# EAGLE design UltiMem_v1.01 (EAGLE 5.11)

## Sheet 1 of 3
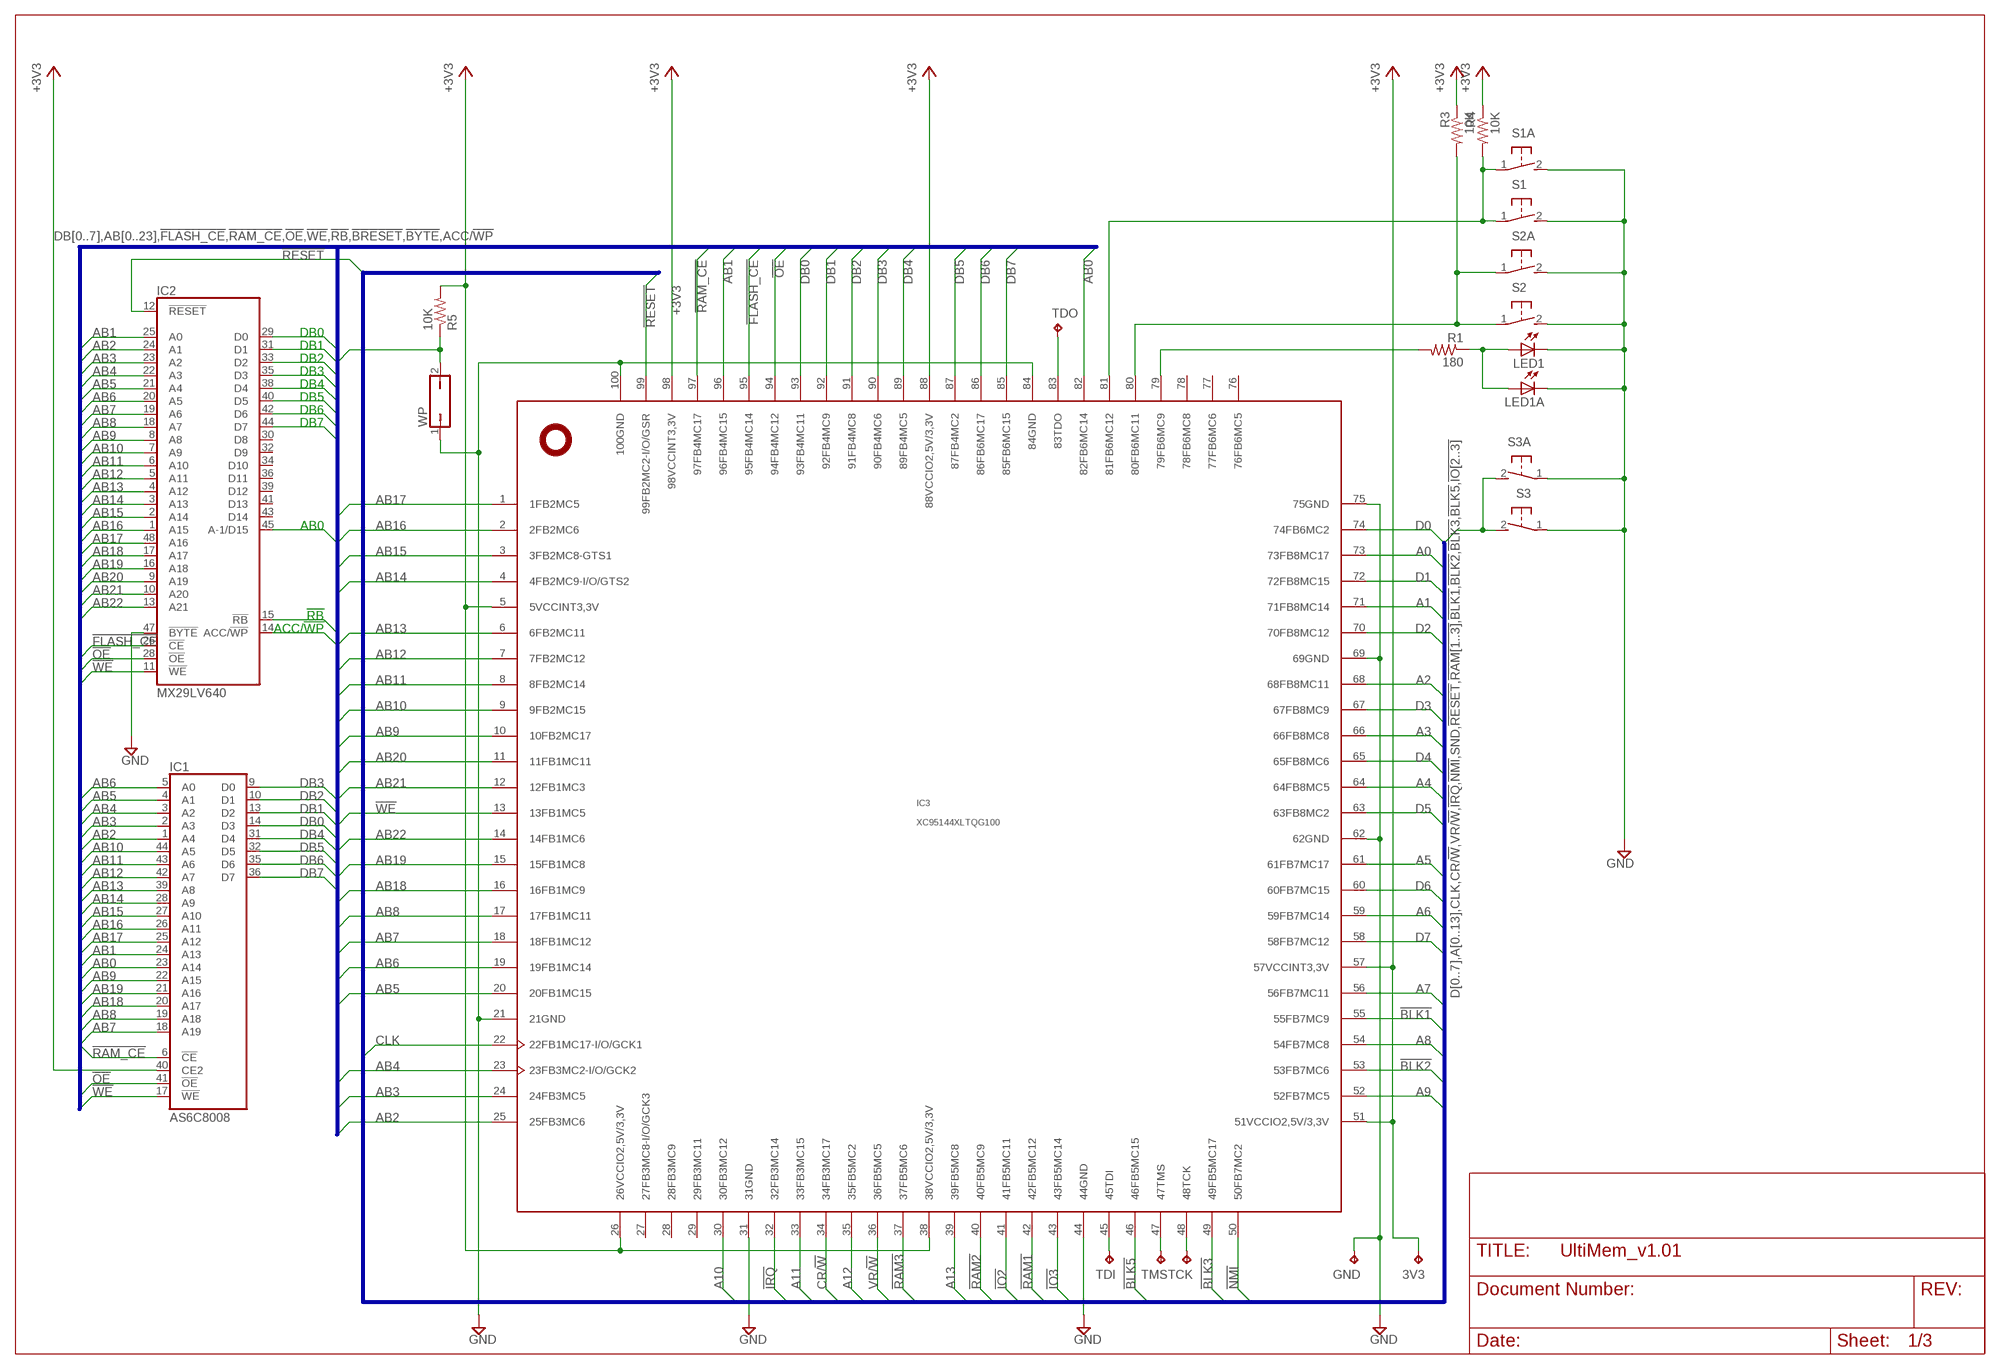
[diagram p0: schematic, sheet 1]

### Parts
3V3  TPTP08R  [TP08R]
GND  TPTP08R  [TP08R]
IC1  AS6C8008  [TSOP44]
IC2  MX29LV640  [TSOP48]
IC3  XC95144XLTQG100  [TQFP100]
LED1  LED3MM  [LED3MM]
LED1A  LED3MM  [LED3MM]
R1  180  R-US_R0402  [R0402]
R3  10K  R-US_R0402  [R0402]
R4  10K  R-US_R0402  [R0402]
R5  10K  R-US_R0402  [R0402]
S1  31-XX  [B3F-31XX]
S1A  31-XX  [B3F-31XX]
S2  31-XX  [B3F-31XX]
S2A  31-XX  [B3F-31XX]
S3  31-XX  [B3F-31XX]
S3A  31-XX  [B3F-31XX]
TCK  TPTP08R  [TP08R]
TDI  TPTP08R  [TP08R]
TDO  TPTP08R  [TP08R]
TMS  TPTP08R  [TP08R]
WP  JP1Q  [JP1]

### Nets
!BLK1: IC3.55(55FB7MC9) ; also sheet 2
!BLK2: IC3.53(53FB7MC6) ; also sheet 2
!BLK3: IC3.49(49FB5MC17) ; also sheet 2
!BLK5: IC3.46(46FB5MC15) ; also sheet 2
!FLASH_CE: IC2.26(!CE) IC3.95(95FB4MC14)
!IO2: IC3.41(41FB5MC11) ; also sheet 2
!IO3: IC3.43(43FB5MC14) ; also sheet 2
!IRQ: IC3.32(32FB3MC14) ; also sheet 2
!NMI: IC3.50(50FB7MC2) ; also sheet 2
!OE: IC1.41(!OE) IC2.28(!OE) IC3.94(94FB4MC12)
!RAM1: IC3.42(42FB5MC12) ; also sheet 2
!RAM2: IC3.40(40FB5MC9) ; also sheet 2
!RAM3: IC3.37(37FB5MC6) ; also sheet 2
!RAM_CE: IC1.6(!CE) IC3.97(97FB4MC17)
!RB: IC2.15(!RB)
!RESET: IC2.12(!RESET) IC3.99(99FB2MC2-I/O/GSR) S3.2(S) S3A.2(S) ; also sheet 2
!WE: IC1.17(!WE) IC2.11(!WE) IC3.13(13FB1MC5)
+3V3: 3V3.TP IC1.40(CE2) IC3.5(5VCCINT3,3V) IC3.26(26VCCIO2,5V/3,3V) IC3.38(38VCCIO2,5V/3,3V) IC3.51(51VCCIO2,5V/3,3V) IC3.57(57VCCINT3,3V) IC3.88(88VCCIO2,5V/3,3V) IC3.98(98VCCINT3,3V) R3.1 R4.1 R5.2 ; also sheet 3
A0: IC3.73(73FB8MC17) ; also sheet 2
A1: IC3.71(71FB8MC14) ; also sheet 2
A2: IC3.68(68FB8MC11) ; also sheet 2
A3: IC3.66(66FB8MC8) ; also sheet 2
A4: IC3.64(64FB8MC5) ; also sheet 2
A5: IC3.61(61FB7MC17) ; also sheet 2
A6: IC3.59(59FB7MC14) ; also sheet 2
A7: IC3.56(56FB7MC11) ; also sheet 2
A8: IC3.54(54FB7MC8) ; also sheet 2
A9: IC3.52(52FB7MC5) ; also sheet 2
A10: IC3.30(30FB3MC12) ; also sheet 2
A11: IC3.33(33FB3MC15) ; also sheet 2
A12: IC3.35(35FB5MC2) ; also sheet 2
A13: IC3.39(39FB5MC8) ; also sheet 2
AB0: IC1.23(A14) IC2.45(A-1/D15) IC3.82(82FB6MC14)
AB1: IC1.24(A13) IC2.25(A0) IC3.96(96FB4MC15)
AB2: IC1.1(A4) IC2.24(A1) IC3.25(25FB3MC6)
AB3: IC1.2(A3) IC2.23(A2) IC3.24(24FB3MC5)
AB4: IC1.3(A2) IC2.22(A3) IC3.23(23FB3MC2-I/O/GCK2)
AB5: IC1.4(A1) IC2.21(A4) IC3.20(20FB1MC15)
AB6: IC1.5(A0) IC2.20(A5) IC3.19(19FB1MC14)
AB7: IC1.18(A19) IC2.19(A6) IC3.18(18FB1MC12)
AB8: IC1.19(A18) IC2.18(A7) IC3.17(17FB1MC11)
AB9: IC1.22(A15) IC2.8(A8) IC3.10(10FB2MC17)
AB10: IC1.44(A5) IC2.7(A9) IC3.9(9FB2MC15)
AB11: IC1.43(A6) IC2.6(A10) IC3.8(8FB2MC14)
AB12: IC1.42(A7) IC2.5(A11) IC3.7(7FB2MC12)
AB13: IC1.39(A8) IC2.4(A12) IC3.6(6FB2MC11)
AB14: IC1.28(A9) IC2.3(A13) IC3.4(4FB2MC9-I/O/GTS2)
AB15: IC1.27(A10) IC2.2(A14) IC3.3(3FB2MC8-GTS1)
AB16: IC1.26(A11) IC2.1(A15) IC3.2(2FB2MC6)
AB17: IC1.25(A12) IC2.48(A16) IC3.1(1FB2MC5)
AB18: IC1.20(A17) IC2.17(A17) IC3.16(16FB1MC9)
AB19: IC1.21(A16) IC2.16(A18) IC3.15(15FB1MC8)
AB20: IC2.9(A19) IC3.11(11FB1MC11)
AB21: IC2.10(A20) IC3.12(12FB1MC3)
AB22: IC2.13(A21) IC3.14(14FB1MC6)
ACC/!WP: IC2.14(ACC/!WP) R5.1 WP.2
CLK: IC3.22(22FB1MC17-I/O/GCK1) ; also sheet 2
CR/!W: IC3.34(34FB3MC17) ; also sheet 2
D0: IC3.74(74FB6MC2) ; also sheet 2
D1: IC3.72(72FB8MC15) ; also sheet 2
D2: IC3.70(70FB8MC12) ; also sheet 2
D3: IC3.67(67FB8MC9) ; also sheet 2
D4: IC3.65(65FB8MC6) ; also sheet 2
D5: IC3.63(63FB8MC2) ; also sheet 2
D6: IC3.60(60FB7MC15) ; also sheet 2
D7: IC3.58(58FB7MC12) ; also sheet 2
DB0: IC1.14(D3) IC2.29(D0) IC3.93(93FB4MC11)
DB1: IC1.13(D2) IC2.31(D1) IC3.92(92FB4MC9)
DB2: IC1.10(D1) IC2.33(D2) IC3.91(91FB4MC8)
DB3: IC1.9(D0) IC2.35(D3) IC3.90(90FB4MC6)
DB4: IC1.31(D4) IC2.38(D4) IC3.89(89FB4MC5)
DB5: IC1.32(D5) IC2.40(D5) IC3.87(87FB4MC2)
DB6: IC1.35(D6) IC2.42(D6) IC3.86(86FB6MC17)
DB7: IC1.36(D7) IC2.44(D7) IC3.85(85FB6MC15)
GND: GND.TP IC2.47(!BYTE) IC3.21(21GND) IC3.31(31GND) IC3.44(44GND) IC3.62(62GND) IC3.69(69GND) IC3.75(75GND) IC3.84(84GND) IC3.100(100GND) LED1.K(C) LED1A.K(C) S1.2(S) S1A.2(S) S2.2(S) S2A.2(S) S3.1(P) S3A.1(P) WP.1 ; also sheet 2,3
N$1: IC3.81(81FB6MC12) R4.2 S1.1(P) S1A.1(P)
N$2: IC3.80(80FB6MC11) R3.2 S2.1(P) S2A.1(P)
N$3: LED1.A LED1A.A R1.1
N$4: IC3.79(79FB6MC9) R1.2
N$5: IC3.45(45TDI) TDI.TP
N$6: IC3.47(47TMS) TMS.TP
N$7: IC3.48(48TCK) TCK.TP
N$8: IC3.83(83TDO) TDO.TP
VR/!W: IC3.36(36FB5MC5) ; also sheet 2
Unconnected: IC2.30(D8) IC2.32(D9) IC2.34(D10) IC2.36(D11) IC2.39(D12) IC2.41(D13) IC2.43(D14) IC3.27(27FB3MC8-I/O/GCK3) IC3.28(28FB3MC9) IC3.29(29FB3MC11) IC3.76(76FB6MC5) IC3.77(77FB6MC6) IC3.78(78FB6MC8)

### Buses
D[0..7],A[0..13],CLK,CR/!W,VR/!W,!IRQ,!NMI,SND,!RESET,!RAM[1..3],!BLK1,!BLK2,!BLK3,!BLK5,!IO[2..3]
DB[0..7],AB[0..23],!FLASH_CE,!RAM_CE,!OE,!WE,!RB,!BRESET,!BYTE,ACC/!WP

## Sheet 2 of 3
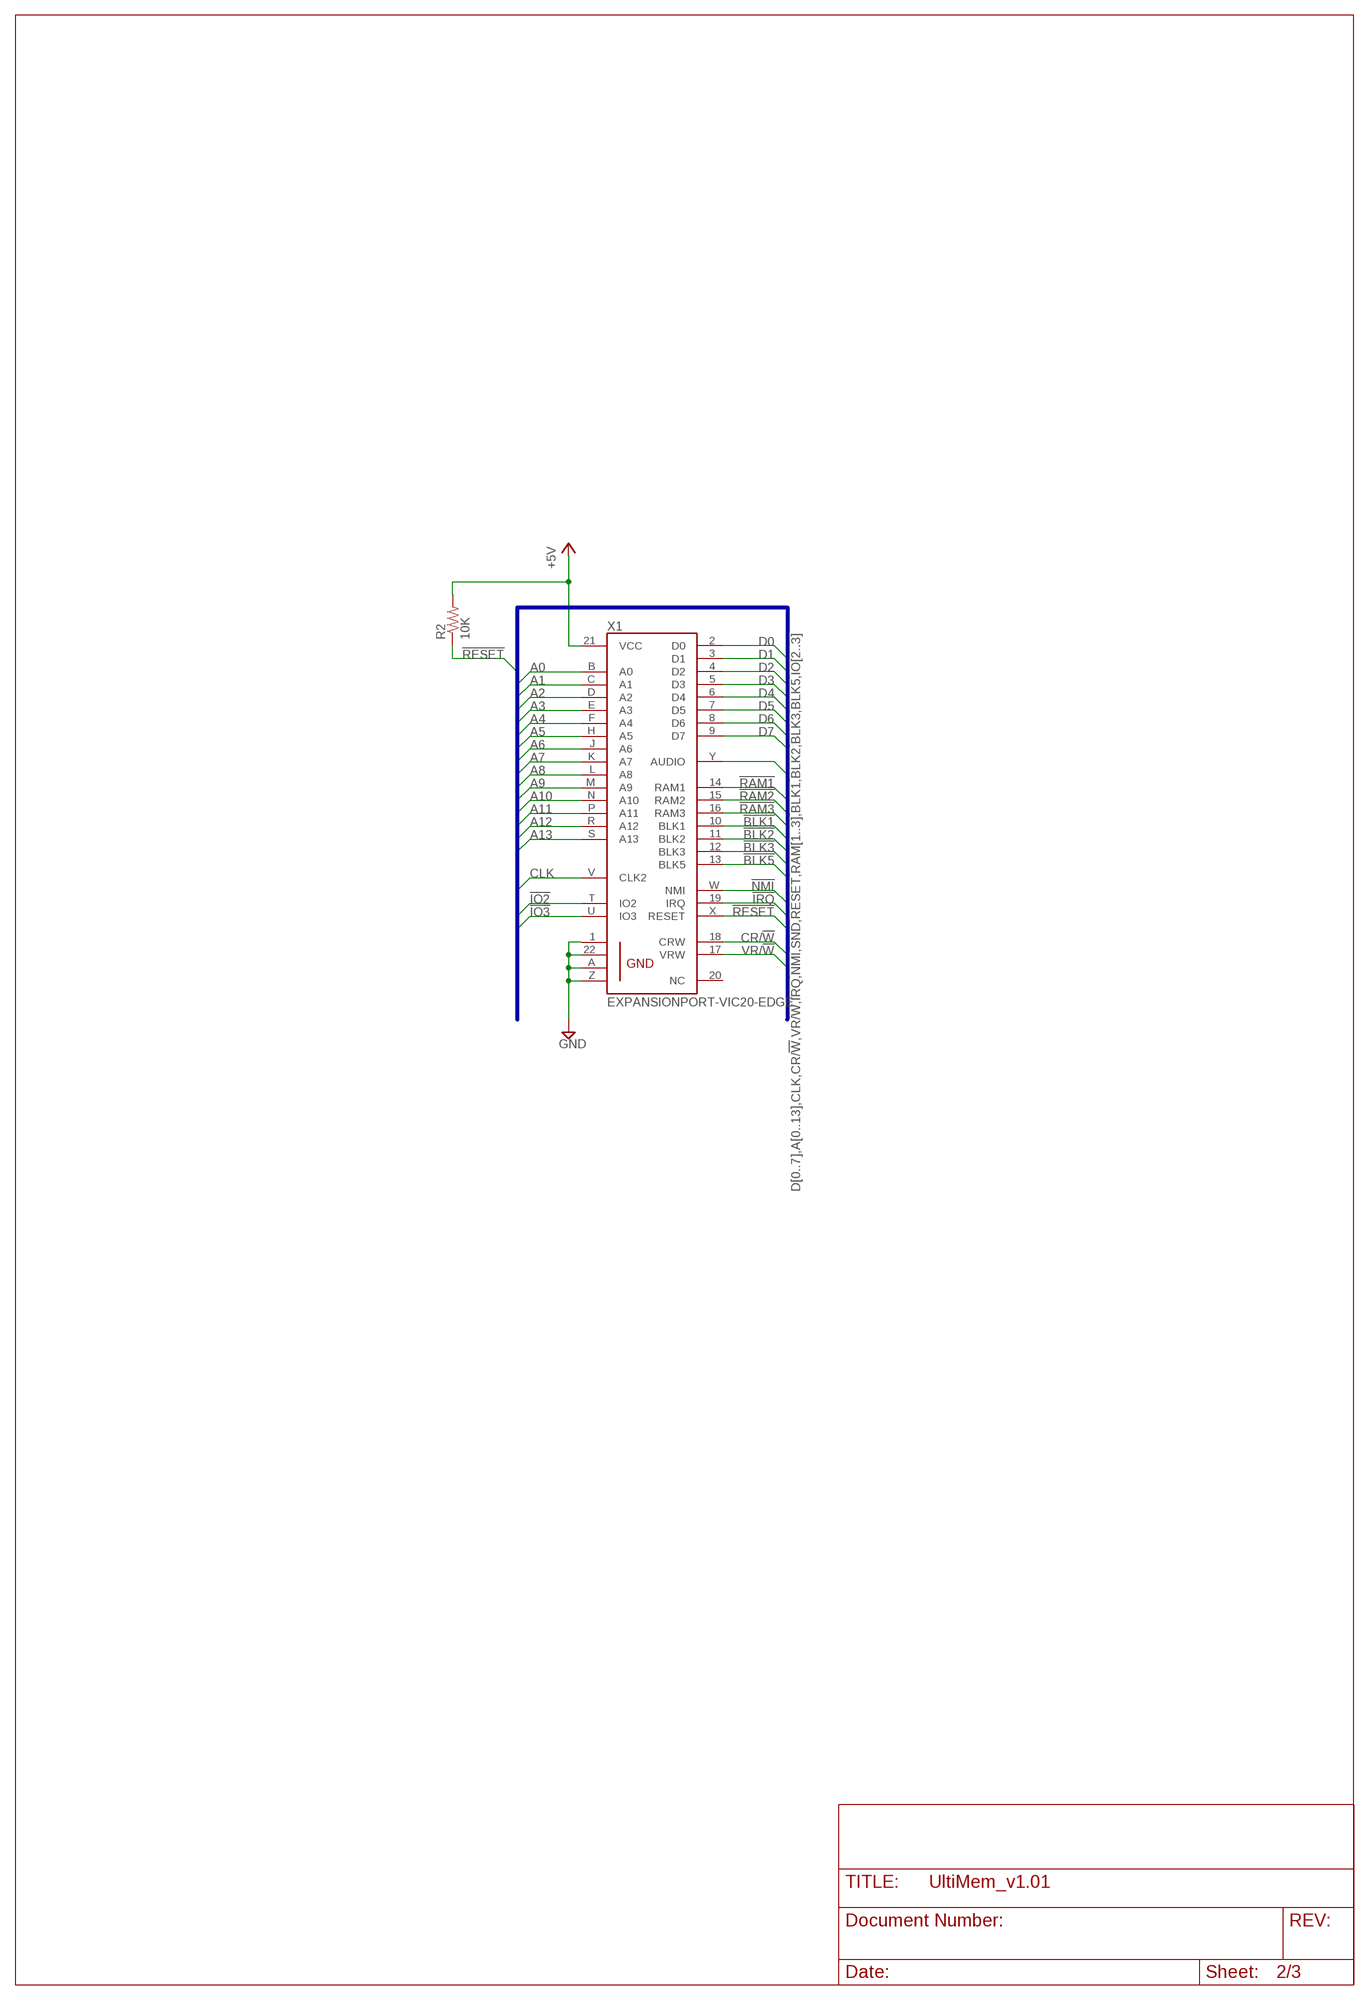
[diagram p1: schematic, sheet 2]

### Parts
R2  10K  R-US_R0402  [R0402]
X1  EXPANSIONPORT-VIC20-EDGE  [MA156-22-2]

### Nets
!BLK1: X1.10(BLK1) ; also sheet 1
!BLK2: X1.11(BLK2) ; also sheet 1
!BLK3: X1.12(BLK3) ; also sheet 1
!BLK5: X1.13(BLK5) ; also sheet 1
!IO2: X1.T(IO2) ; also sheet 1
!IO3: X1.U(IO3) ; also sheet 1
!IRQ: X1.19(IRQ) ; also sheet 1
!NMI: X1.W(NMI) ; also sheet 1
!RAM1: X1.14(RAM1) ; also sheet 1
!RAM2: X1.15(RAM2) ; also sheet 1
!RAM3: X1.16(RAM3) ; also sheet 1
!RESET: R2.1 X1.X(RESET) ; also sheet 1
+5V: R2.2 X1.21(VCC) ; also sheet 3
A0: X1.B(A0) ; also sheet 1
A1: X1.C(A1) ; also sheet 1
A2: X1.D(A2) ; also sheet 1
A3: X1.E(A3) ; also sheet 1
A4: X1.F(A4) ; also sheet 1
A5: X1.H(A5) ; also sheet 1
A6: X1.J(A6) ; also sheet 1
A7: X1.K(A7) ; also sheet 1
A8: X1.L(A8) ; also sheet 1
A9: X1.M(A9) ; also sheet 1
A10: X1.N(A10) ; also sheet 1
A11: X1.P(A11) ; also sheet 1
A12: X1.R(A12) ; also sheet 1
A13: X1.S(A13) ; also sheet 1
CLK: X1.V(CLK2) ; also sheet 1
CR/!W: X1.18(CRW) ; also sheet 1
D0: X1.2(D0) ; also sheet 1
D1: X1.3(D1) ; also sheet 1
D2: X1.4(D2) ; also sheet 1
D3: X1.5(D3) ; also sheet 1
D4: X1.6(D4) ; also sheet 1
D5: X1.7(D5) ; also sheet 1
D6: X1.8(D6) ; also sheet 1
D7: X1.9(D7) ; also sheet 1
GND: X1.1(GND1) X1.22(GND2) X1.A(GND3) X1.Z(GND4) ; also sheet 1,3
SND: X1.Y(AUDIO)
VR/!W: X1.17(VRW) ; also sheet 1
Unconnected: X1.20(NC)

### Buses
D[0..7],A[0..13],CLK,CR/!W,VR/!W,!IRQ,!NMI,SND,!RESET,!RAM[1..3],!BLK1,!BLK2,!BLK3,!BLK5,!IO[2..3]

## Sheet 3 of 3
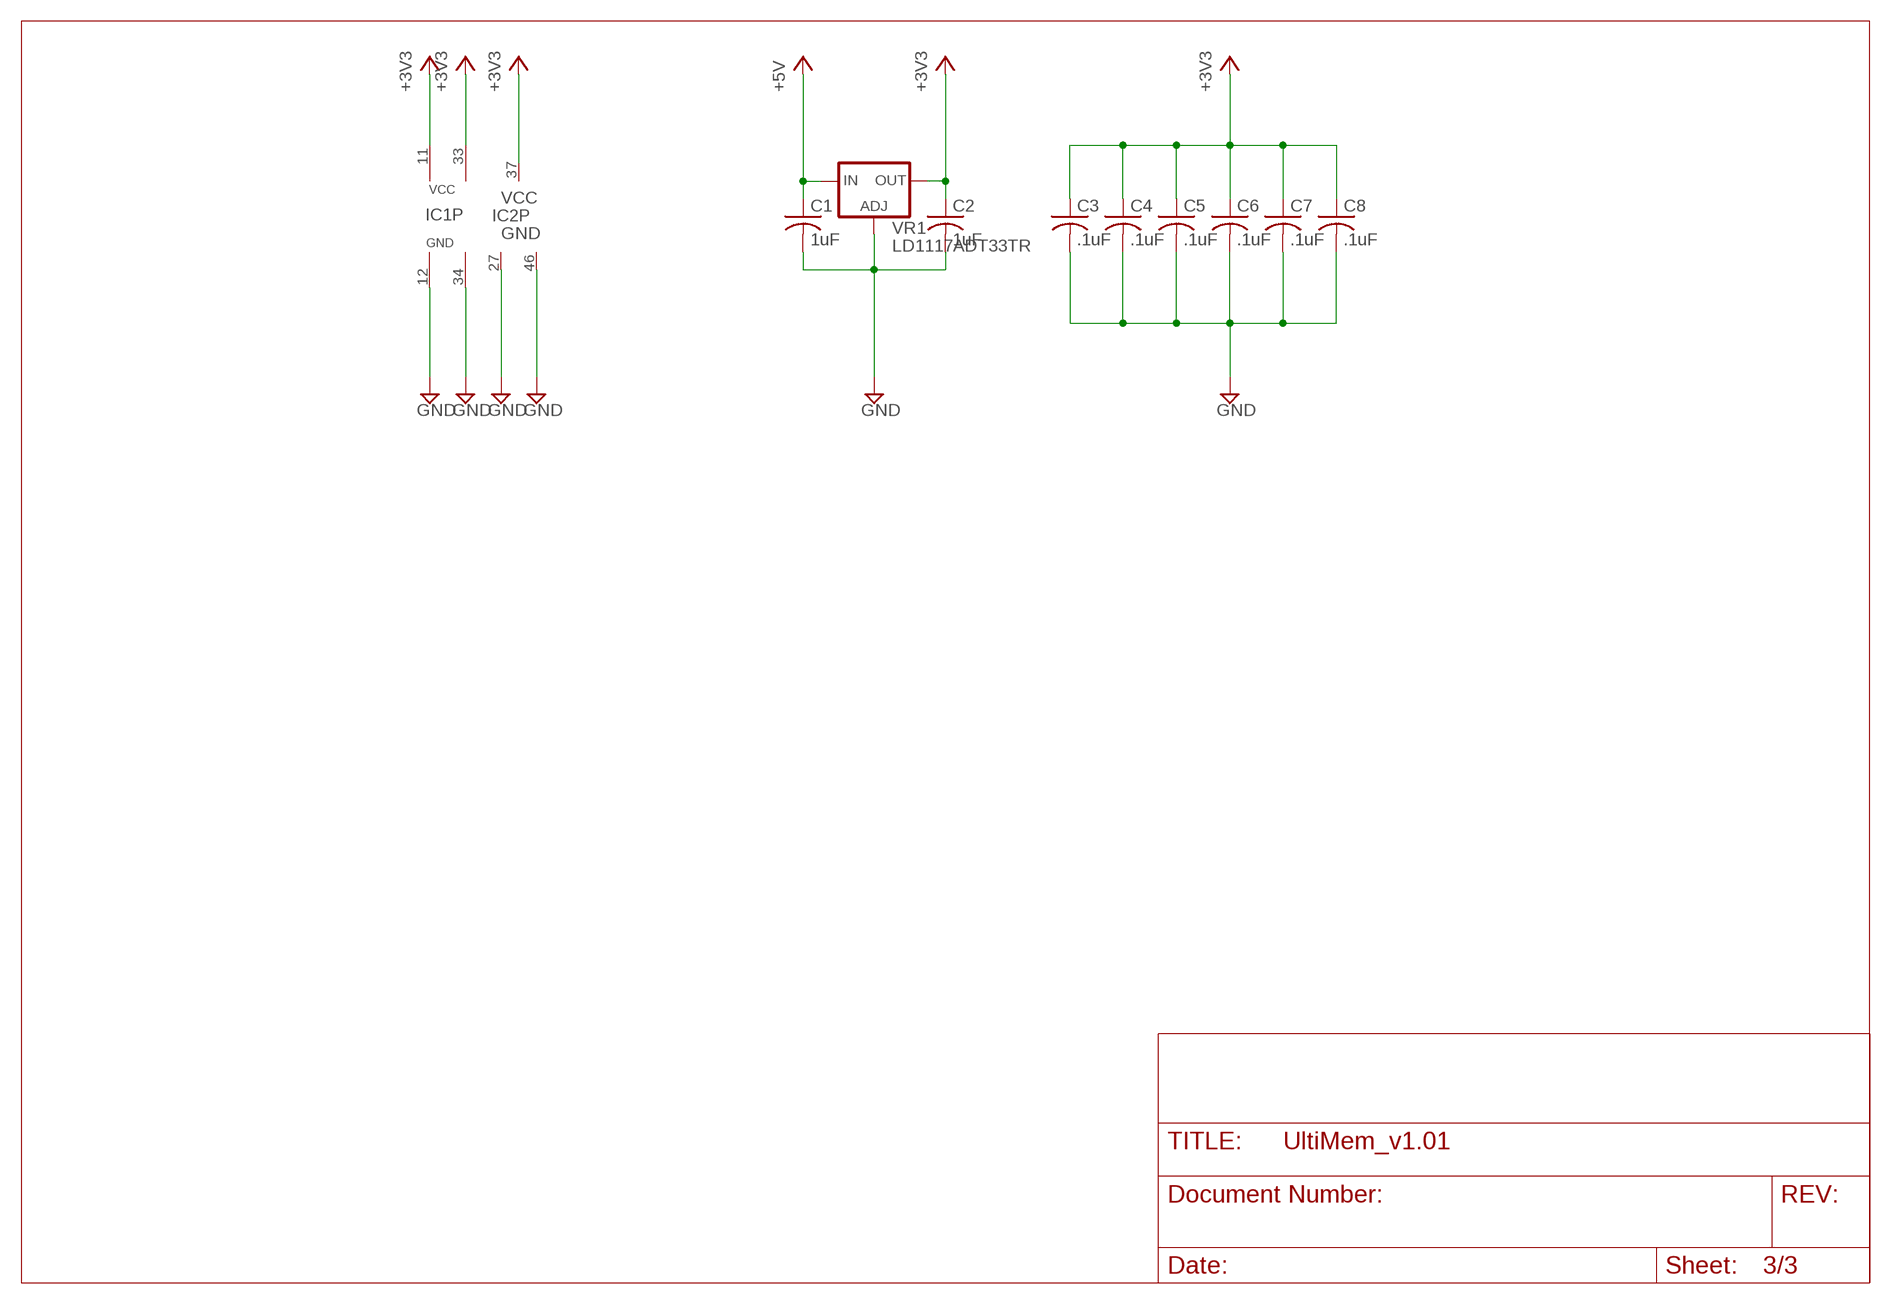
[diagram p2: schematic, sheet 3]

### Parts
C1  1uF  C-USC0402  [C0402]
C2  1uF  C-USC0402  [C0402]
C3  .1uF  C-USC0402  [C0402]
C4  .1uF  C-USC0402  [C0402]
C5  .1uF  C-USC0402  [C0402]
C6  .1uF  C-USC0402  [C0402]
C7  .1uF  C-USC0402  [C0402]
C8  .1uF  C-USC0402  [C0402]
VR1  LD1117ADT33TR  LD117ADT33TR  [DPACK]

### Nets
+3V3: C2.1 C3.1 C4.1 C5.1 C6.1 C7.1 C8.1 IC1.11(VCC) IC1.33(VCC) IC2.37(VCC) VR1.4(OUT) ; also sheet 1
+5V: C1.1 VR1.3(IN) ; also sheet 2
GND: C1.2 C2.2 C3.2 C4.2 C5.2 C6.2 C7.2 C8.2 IC1.12(GND) IC1.34(GND) IC2.27(GND) IC2.46(GND) VR1.1(ADJ) ; also sheet 1,2

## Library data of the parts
3V3 GND TCK TDI TDO TMS = testpad:TP: Test pad
C1-C8 = rcl:C-US: CAPACITOR, American symbol
IC1 = memory--alliance:AS6C8008
IC2 = memory-macronix:MX29LV640
IC3 = xilinx_xc95XXXxl:XC95144XLTQG100
LED1 LED1A = led:LED: LED
R1 R3-R5 = rcl:R-US_: RESISTOR, American symbol
R2 = resistor:R-US_: RESISTOR, American symbol
S1 S1A S2 S2A S3 S3A = switch-omron:31-XX: OMRON SWITCH; MPN: B3F-3100; OC_FARNELL: 959704; OC_NEWARK: 36M3582
VR1 = v-reg:LD117A?*: Low drop fixed and adjustable positive voltage regulators 1 A Source: http://www.st.com/stonline/products/literature/ds/7194/ld1117axx.pdf
WP = jumper:JP1Q: JUMPER
X1 = 0RB_Commodore:EXPANSIONPORT-VIC20-EDGE: Expansionport for the Commodore VIC-20, edge version

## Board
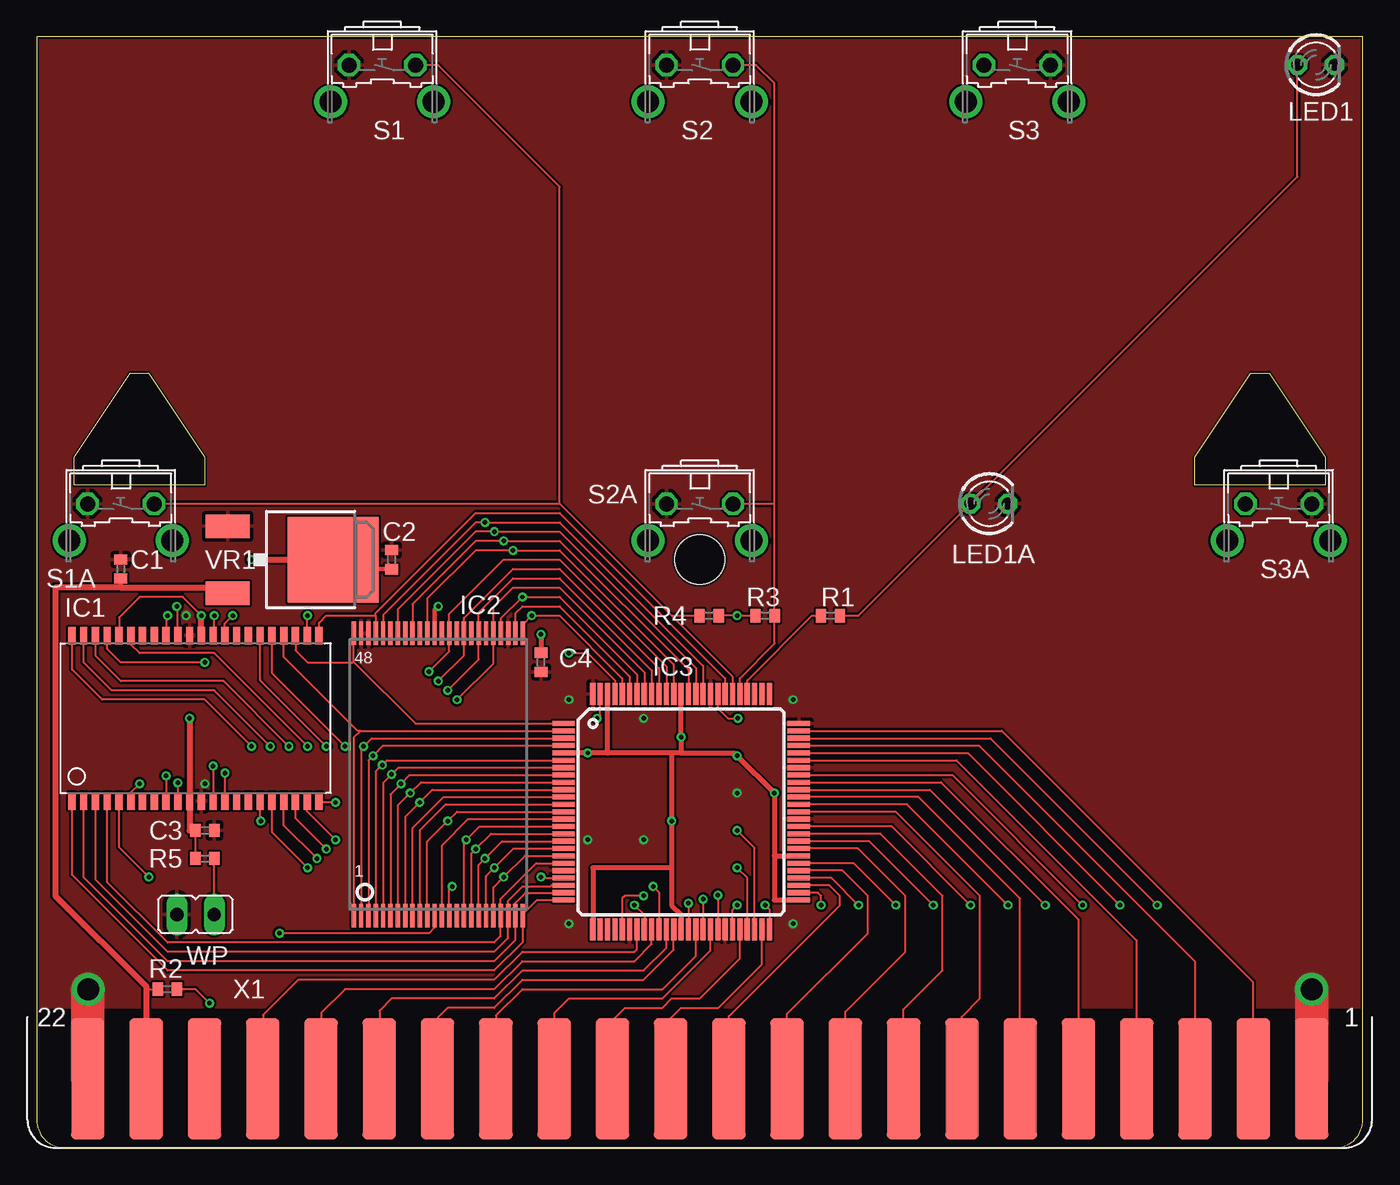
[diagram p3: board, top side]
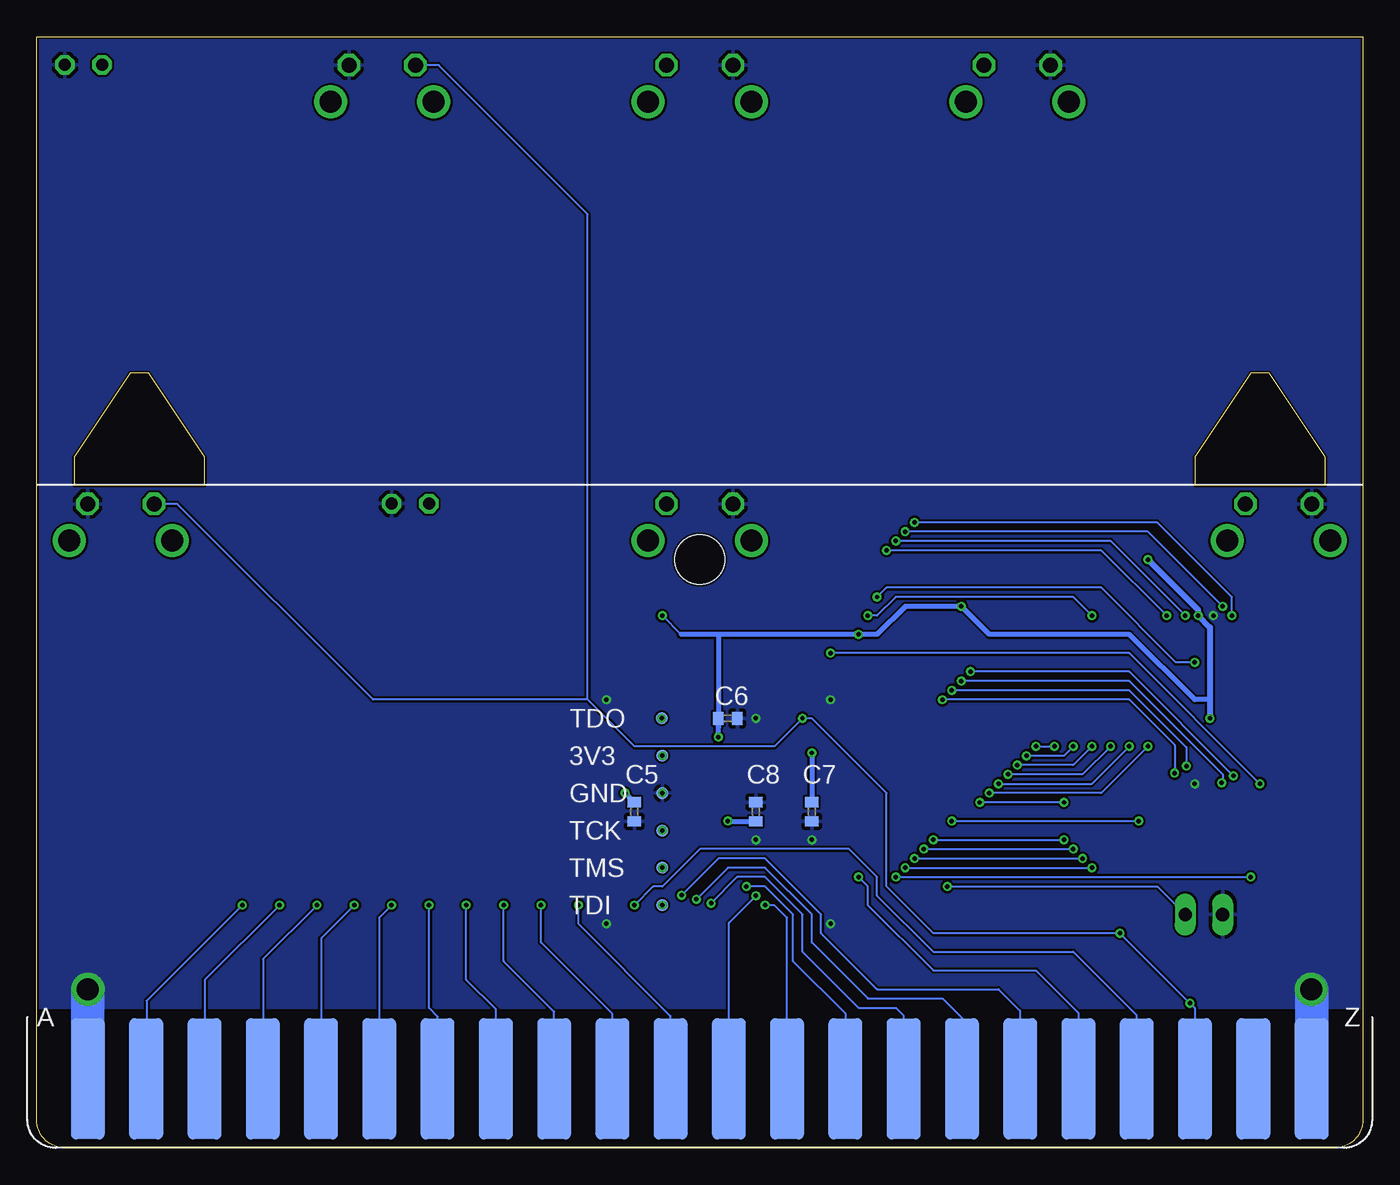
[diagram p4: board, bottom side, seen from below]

Size 90.17 x 75.56 mm. Coordinates in mm from the lower left corner, seen from the top.
Outline: 90.17,75.56 0,75.56 0,1.91 arc90 1.91,0 88.27,0 arc90 90.17,1.91 90.17,75.56
Outline: 2.54,45.09 2.54,46.99 6.35,52.7 7.62,52.7 11.43,46.99 11.43,45.09 2.54,45.09
Outline: 78.74,45.09 78.74,46.99 82.55,52.7 83.82,52.7 87.63,46.99 87.63,45.09 78.74,45.09
Copper layers (1*16): Top 0.035mm / dielectric 1.5mm / Bottom 0.035mm
Design rules "hackvana *": minimum track width 6mil, minimum drill 0.3mm, track to track 0.1501mm, track to pad 0.1501mm, pad to pad 0.1501mm, via to via 0.1501mm, smd to smd 0mil, copper to edge 6mil, drill to drill 6mil, minimum pad ring 10mil, minimum via ring 6mil, stop-mask expansion 2mil, vias tented up to drill 100mil, thermal gap 10mil
Holes 3.38 mm at 45.09,40.01

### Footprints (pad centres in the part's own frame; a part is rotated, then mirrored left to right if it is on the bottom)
TP08R = smd 0.8 x 0.8: TP 0,0
C0402 = smd 0.7 x 0.9: 1 -0.65,0; 2 0.65,0
TSOP44 = smd 0.5 x 1.2: 1 -8.4,-5.627; 2 -7.6,-5.627; 3 -6.8,-5.627; 4 -6,-5.627; 5 -5.2,-5.627; 6 -4.4,-5.627; 7 -3.6,-5.627; 8 -2.8,-5.627; 9 -2,-5.627; 10 -1.2,-5.627; 11 -0.4,-5.627; 12 0.4,-5.627; 13 1.2,-5.627; 14 2,-5.627; 15 2.8,-5.627; 16 3.6,-5.627; 17 4.4,-5.627; 18 5.2,-5.627; 19 6,-5.627; 20 6.8,-5.627; 21 7.6,-5.627; 22 8.4,-5.627; 23 8.4,5.627; 24 7.6,5.627; 25 6.8,5.627; 26 6,5.627; 27 5.2,5.627; 28 4.4,5.627; 29 3.6,5.627; 30 2.8,5.627; 31 2,5.627; 32 1.2,5.627; 33 0.4,5.627; 34 -0.4,5.627; 35 -1.2,5.627; 36 -2,5.627; 37 -2.8,5.627; 38 -3.6,5.627; 39 -4.4,5.627; 40 -5.2,5.627; 41 -6,5.627; 42 -6.8,5.627; 43 -7.6,5.627; 44 -8.4,5.627
TSOP48 = smd 1.6 x 0.3: 1 -9.6,5.75; 2 -9.6,5.25; 3 -9.6,4.75; 4 -9.6,4.25; 5 -9.6,3.75; 6 -9.6,3.25; 7 -9.6,2.75; 8 -9.6,2.25; 9 -9.6,1.75; 10 -9.6,1.25; 11 -9.6,0.75; 12 -9.6,0.25; 13 -9.6,-0.25; 14 -9.6,-0.75; 15 -9.6,-1.25; 16 -9.6,-1.75; 17 -9.6,-2.25; 18 -9.6,-2.75; 19 -9.6,-3.25; 20 -9.6,-3.75; 21 -9.6,-4.25; 22 -9.6,-4.75; 23 -9.6,-5.25; 24 -9.6,-5.75; 25 9.6,-5.75; 26 9.6,-5.25; 27 9.6,-4.75; 28 9.6,-4.25; 29 9.6,-3.75; 30 9.6,-3.25; 31 9.6,-2.75; 32 9.6,-2.25; 33 9.6,-1.75; 34 9.6,-1.25; 35 9.6,-0.75; 36 9.6,-0.25; 37 9.6,0.25; 38 9.6,0.75; 39 9.6,1.25; 40 9.6,1.75; 41 9.6,2.25; 42 9.6,2.75; 43 9.6,3.25; 44 9.6,3.75; 45 9.6,4.25; 46 9.6,4.75; 47 9.6,5.25; 48 9.6,5.75
TQFP100 = smd 1.5 x 0.35: 1 -8,6; 2 -8,5.5; 3 -8,5; 4 -8,4.5; 5 -8,4; 6 -8,3.5; 7 -8,3; 8 -8,2.5; 9 -8,2; 10 -8,1.5; 11 -8,1; 12 -8,0.5; 13 -8,0; 14 -8,-0.5; 15 -8,-1; 16 -8,-1.5; 17 -8,-2; 18 -8,-2.5; 19 -8,-3; 20 -8,-3.5; 21 -8,-4; 22 -8,-4.5; 23 -8,-5; 24 -8,-5.5; 25 -8,-6; 51 8,-6; 52 8,-5.5; 53 8,-5; 54 8,-4.5; 55 8,-4; 56 8,-3.5; 57 8,-3; 58 8,-2.5; 59 8,-2; 60 8,-1.5; 61 8,-1; 62 8,-0.5; 63 8,0; 64 8,0.5; 65 8,1; 66 8,1.5; 67 8,2; 68 8,2.5; 69 8,3; 70 8,3.5; 71 8,4; 72 8,4.5; 73 8,5; 74 8,5.5; 75 8,6 | smd 0.35 x 1.5: 26 -6,-8; 27 -5.5,-8; 28 -5,-8; 29 -4.5,-8; 30 -4,-8; 31 -3.5,-8; 32 -3,-8; 33 -2.5,-8; 34 -2,-8; 35 -1.5,-8; 36 -1,-8; 37 -0.5,-8; 38 0,-8; 39 0.5,-8; 40 1,-8; 41 1.5,-8; 42 2,-8; 43 2.5,-8; 44 3,-8; 45 3.5,-8; 46 4,-8; 47 4.5,-8; 48 5,-8; 49 5.5,-8; 50 6,-8; 76 6,8; 77 5.5,8; 78 5,8; 79 4.5,8; 80 4,8; 81 3.5,8; 82 3,8; 83 2.5,8; 84 2,8; 85 1.5,8; 86 1,8; 87 0.5,8; 88 0,8; 89 -0.5,8; 90 -1,8; 91 -1.5,8; 92 -2,8; 93 -2.5,8; 94 -3,8; 95 -3.5,8; 96 -4,8; 97 -4.5,8; 98 -5,8; 99 -5.5,8; 100 -6,8
LED3MM = drill 0.813 octagon: A -1.27,0; K 1.27,0
R0402 = smd 0.7 x 0.9: 1 -0.65,0; 2 0.65,0
B3F-31XX = drill 1.016 octagon: 1 -2.261,-1.245; 2 2.261,-1.245 | drill 1.499 pad 2.159: 3 -3.505,1.245; 4 3.505,1.245
DPACK = smd 1.6 x 3: 1 -2.28,-4.8; 3 2.28,-4.8 | smd 5.8 x 6.2: 4 0,2.38
JP1 = drill 0.914 long: 1 0,-1.27; 2 0,1.27
MA156-22-2 = smd 2.286 x 8.255: 1 41.605,-0.381; 2 37.643,-0.381; 3 33.68,-0.381; 4 29.718,-0.381; 5 25.756,-0.381; 6 21.793,-0.381; 7 17.831,-0.381; 8 13.868,-0.381; 9 9.906,-0.381; 10 5.944,-0.381; 11 1.981,-0.381; 12 -1.981,-0.381; 13 -5.944,-0.381; 14 -9.906,-0.381; 15 -13.868,-0.381; 16 -17.831,-0.381; 17 -21.793,-0.381; 18 -25.756,-0.381; 19 -29.718,-0.381; 20 -33.68,-0.381; 21 -37.643,-0.381; 22 -41.605,-0.381 | smd 2.286 x 8.255 bottom: A 41.605,-0.381; B 37.643,-0.381; C 33.68,-0.381; D 29.718,-0.381; E 25.756,-0.381; F 21.793,-0.381; H 17.831,-0.381; J 13.868,-0.381; K 9.906,-0.381; L 5.944,-0.381; M 1.981,-0.381; N -1.981,-0.381; P -5.944,-0.381; R -9.906,-0.381; S -13.868,-0.381; T -17.831,-0.381; U -21.793,-0.381; V -25.756,-0.381; W -29.718,-0.381; X -33.68,-0.381; Y -37.643,-0.381; Z -41.605,-0.381

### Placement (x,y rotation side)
3V3  47.62,26.67 90 bottom
C1  5.72,39.37 90 top
C2  24.13,40.01 90 top
C3  11.43,21.59 0 top
C4  34.29,33.02 270 top
C5  49.53,22.86 270 bottom
C6  43.18,29.21 0 bottom
C7  37.47,22.86 270 bottom
C8  41.27,22.86 90 bottom
GND  47.62,24.13 90 bottom
IC1  10.8,29.21 0 top
IC2  27.3,25.4 90 top
IC3  43.81,22.86 0 top
LED1  87,73.66 0 top
LED1A  64.77,43.81 0 top
R1  53.98,36.2 180 top
R2  8.89,10.79 180 top
R3  49.53,36.2 0 top
R4  45.72,36.2 180 top
R5  11.43,19.68 180 top
S1  23.5,72.39 180 top
S1A  5.72,42.55 180 top
S2  45.09,72.39 180 top
S2A  45.09,42.55 180 top
S3  66.67,72.39 180 top
S3A  84.45,42.55 180 top
TCK  47.62,21.59 90 bottom
TDI  47.62,16.51 90 bottom
TDO  47.68,29.21 90 bottom
TMS  47.62,19.05 90 bottom
VR1  17.78,40.01 270 top
WP  10.8,15.88 270 top
X1  45.09,5.08 0 top

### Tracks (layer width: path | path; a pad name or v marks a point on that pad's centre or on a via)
!BLK1
  Top 0.152: IC3.55 54.8,18.86 56.52,17.14 56.52,14.61 51.02,9.11 X1.10
!BLK2
  Top 0.152: IC3.53 53.9,17.86 54.61,17.14 54.61,16.51 47.06,8.96 X1.11
!BLK3
  Top 0.152: X1.12 43.1,8.81 43.81,9.53 46.36,9.53 49.31,12.48 IC3.49
!BLK5
  Top 0.152: IC3.46 47.81,12.89 45.09,10.16 43.18,10.16 42.55,9.53 40.01,9.53 39.14,8.66 X1.13
!FLASH_CE
  Top 0.152: IC2.26 32.55,36.37 33.02,36.83 35.56,36.83 40.31,32.08 IC3.95
!IO2  (via drill 0.3)
  Top 0.152: v45.31,16.91 IC3.41
  Bottom 0.152: v45.31,16.91 43.18,19.05 40.64,19.05 37.47,15.88 37.47,13.97 33.66,10.16 28.57,10.16 27.26,8.85 X1.T
!IO3  (via drill 0.3)
  Top 0.152: v46.31,17.18 IC3.43
  Bottom 0.152: v46.31,17.18 43.81,19.68 40.64,19.68 36.83,15.88 36.83,14.61 33.02,10.79 24.77,10.79 23.3,9.33 23.3,4.71 X1.U
!IRQ
  Top 0.152: IC3.32 40.81,13.51 40.64,13.34 33.02,13.34 31.12,11.43 17.78,11.43 15.38,9.03 15.38,4.72 X1.19
!NMI  (via drill 0.3)
  Top 0.152: v49.53,16.51 49.81,16.23 IC3.50
  Bottom 0.152: v49.53,16.51 48.26,17.78 47.62,17.78 45.09,20.32 34.92,20.32 33.02,18.41 33.02,17.14 29.21,13.34 19.69,13.34 15.38,9.03 15.38,4.72 X1.W
!OE  (via drill 0.3)
  Top 0.152: IC2.28 31.55,36 v33.02,37.47 35.56,37.47 40.81,32.21 IC3.94 | IC1.41 4.8,33.94 5.72,33.02 v11.43,33.02
  Bottom 0.152: v11.43,33.02 12.7,33.02 17.78,38.1 32.39,38.1 v33.02,37.47
!RAM1
  Top 0.152: IC3.42 45.81,13.43 42.55,10.16 36.2,10.16 35.18,9.15 X1.14
!RAM2
  Top 0.152: IC3.40 44.81,13.06 42.55,10.79 33.02,10.79 31.22,9 X1.15
!RAM3
  Top 0.152: IC3.37 43.31,13.47 41.27,11.43 33.02,11.43 31.12,9.53 27.94,9.53 27.26,8.85 X1.16
!RAM_CE  (via drill 0.3)
  Top 0.152: IC1.6 6.4,24.18 v6.98,24.77 | IC3.97 39.31,31.8 37.47,33.66 v36.2,33.66
  Bottom 0.152: v6.98,24.77 15.88,33.66 v36.2,33.66
!RESET  (via drill 0.3)
  Top 0.152: v38.1,29.21 38.31,29.43 IC3.99 | R2.1 10.8,10.79 v11.75,9.84 | IC2.12 27.05,14.99 26.67,14.61 v16.51,14.61
  Bottom 0.152: X1.X 11.42,4.72 11.42,9.52 v11.75,9.84 v16.51,14.61 29.21,14.61 32.39,17.78 32.39,24.13 37.47,29.21 v38.1,29.21 40.01,27.3 49.53,27.3 52.7,30.48 | S3.2 62.84,73.64 52.7,63.5 52.7,30.48 | S3A.2 80.62,43.79 67.31,30.48 52.7,30.48
!WE  (via drill 0.3)
  Top 0.152: IC2.11 26.55,20.84 v27.94,22.23 28.57,22.86 IC3.13 | IC1.17 15.2,22.27 v15.24,22.23
  Bottom 0.152: v27.94,22.23 v15.24,22.23
+3V3  (via drill 0.3)
  Top 0.152: IC1.40 5.59,36.08 6.98,37.47 9.93,37.47 v11.2,36.2 | R4.1 v47.62,36.2 R3.1 | C3.1 R5.2
  Top 0.305: IC2.37 27.05,36.58 v27.3,36.83 | C2.1 20.81,39.35 arc-90 VR1.4
  Top 0.33: 38.81,26.86 IC3.98 | IC3.5 v37.47,26.86 38.81,26.86 | IC3.51 50.16,16.86 50.16,19.86 | 50.16,19.86 IC3.57 | 50.16,19.86 v50.16,24.13 3V3.TP 47.44,26.86 43.81,26.86 | IC3.88 v43.81,27.94 43.81,26.86 | 43.18,26.86 38.81,26.86 | 43.81,26.86 43.18,26.86 | IC3.38 43.81,15.88 43.18,16.51 43.18,19.05 | 43.18,26.86 v43.18,22.23 43.18,19.05 | IC3.26 37.81,19.05 43.18,19.05
  Top 0.356: v34.29,34.92 C4.1
  Top 0.406: IC1.33 v11.2,36.2 | v10.4,29.21 IC1.11 10.4,21.59 C3.1 | v14.61,40.01 VR1.4
  Bottom 0.152: 46.36,34.92 v47.62,36.2
  Bottom 0.33: C6.1 43.83,27.95 | 43.81,34.92 43.81,29.21
  Bottom 0.356: v37.47,26.86 C7.1 | C8.1 43.16,22.21 v43.18,22.23 | 43.83,27.95 v43.81,27.94 | C5.1 v50.16,24.13 | 10.4,30.48 11.43,30.48 15.88,34.92 25.4,34.92 v27.3,36.83 31.12,36.83 33.02,34.92 v34.29,34.92 43.81,34.92 46.36,34.92 | 43.81,28.57 43.81,29.21 C6.1
  Bottom 0.406: v10.4,29.21 10.4,30.48 10.4,35.4 v11.2,36.2 11.2,36.59 v14.61,40.01
  other vias: 47.62,26.67
+5V
  Top 0.152: 7.46,10.79 R2.2
  Top 0.305: C1.1 5.72,38.1
  Top 0.406: 7.44,10.97 7.46,10.95 | 12.7,38.1 5.72,38.1 1.27,38.1 1.27,17.14 7.44,10.97 | 7.44,10.79 7.46,10.79 | 7.44,10.79 X1.21 | 7.44,10.97 7.44,10.79
  Top 0.813: 12.7,38.1 12.7,37.73 VR1.3
A0  (via drill 0.3)
  Top 0.152: IC3.73 64.85,27.86 v76.2,16.51
  Bottom 0.152: v76.2,16.51 82.7,10.01 82.7,4.72 X1.B
A1  (via drill 0.3)
  Top 0.152: IC3.71 63.31,26.86 v73.66,16.51
  Bottom 0.152: v73.66,16.51 78.74,11.43 78.74,4.72 X1.C
A2  (via drill 0.3)
  Top 0.152: IC3.68 62.27,25.36 v71.12,16.51
  Bottom 0.152: v71.12,16.51 74.78,12.85 74.78,4.72 X1.D
A3  (via drill 0.3)
  Top 0.152: IC3.66 60.73,24.36 v68.58,16.51
  Bottom 0.152: v68.58,16.51 70.82,14.27 70.82,4.72 X1.E
A4  (via drill 0.3)
  Top 0.152: IC3.64 59.19,23.36 v66.04,16.51
  Bottom 0.152: v66.04,16.51 66.86,15.69 66.86,4.71 X1.F
A5  (via drill 0.3)
  Top 0.152: IC3.61 58.15,21.86 v63.5,16.51
  Bottom 0.152: v63.5,16.51 63.5,9.53 62.9,8.93 62.9,4.71 X1.H
A6  (via drill 0.3)
  Top 0.152: IC3.59 56.61,20.86 v60.96,16.51
  Bottom 0.152: v60.96,16.51 60.96,11.43 58.94,9.41 X1.J
A7  (via drill 0.3)
  Top 0.152: IC3.56 55.57,19.36 v58.42,16.51
  Bottom 0.152: v58.42,16.51 58.42,12.7 54.98,9.26 54.98,4.71 X1.K
A8  (via drill 0.3)
  Top 0.152: IC3.54 54.03,18.36 v55.88,16.51
  Bottom 0.152: v55.88,16.51 55.88,13.97 51.02,9.11 X1.L
A9  (via drill 0.3)
  Top 0.152: IC3.52 53.12,17.36 53.34,17.14 v53.34,16.51
  Bottom 0.152: v53.34,16.51 53.34,15.24 47.06,8.96 X1.M
A10  (via drill 0.3)
  Top 0.152: IC3.30 39.81,16.95 40.01,17.14 v41.27,17.14
  Bottom 0.152: X1.N 43.1,15.32 v41.27,17.14
A11  (via drill 0.3)
  Top 0.152: IC3.33 41.31,15.84 v40.64,16.51
  Bottom 0.152: v40.64,16.51 40.01,16.51 39.14,15.65 X1.P
A12  (via drill 0.3)
  Top 0.152: IC3.35 42.31,17.38 v41.91,17.78
  Bottom 0.152: v41.91,17.78 40.64,17.78 38.73,15.88 38.73,12.7 35.18,9.15 X1.R
A13  (via drill 0.3)
  Top 0.152: v44.31,16.64 IC3.39
  Bottom 0.152: v44.31,16.64 42.55,18.41 40.64,18.41 38.1,15.88 38.1,13.34 34.29,9.53 31.75,9.53 31.22,9 X1.S
AB0
  Top 0.152: 23.05,36.2 IC2.45 | 23.05,36.2 23.05,36.39 29.84,43.18 35.56,43.18 46.81,31.93 IC3.82 | IC1.23 19.2,35.7 19.69,36.2 23.05,36.2
AB1  (via drill 0.3)
  Top 0.152: IC1.24 18.39,36.17 v18.41,36.2 | IC2.25 33.05,35.59 v33.66,36.2 35.56,36.2 39.81,31.94 IC3.96
  Bottom 0.152: v33.66,36.2 33.02,36.2 31.75,37.47 19.69,37.47 v18.41,36.2
AB2
  Top 0.152: IC3.25 34.01,16.86 33.05,15.91 IC2.24 33.05,14.01 31.12,12.06 8.89,12.06 2.4,18.56 IC1.1
AB3
  Top 0.152: IC3.24 33.23,17.36 32.55,16.68 IC2.23 32.55,14.14 31.12,12.7 8.89,12.7 3.2,18.39 IC1.2
AB4
  Top 0.152: IC3.23 35.01,17.86 34.92,17.78 33.02,17.78 32.05,16.82 IC2.22 32.05,14.28 31.12,13.34 8.89,13.34 3.99,18.23 IC1.3
AB5
  Top 0.152: IC3.20 33.97,19.36 31.55,16.95 IC2.21 31.55,14.41 31.12,13.97 8.89,13.97 4.8,18.07 IC1.4
AB6  (via drill 0.3)
  Top 0.152: IC2.20 31.05,17.72 v31.75,18.41 33.2,19.86 IC3.19 | IC1.5 5.59,20.44 v7.62,18.41
  Bottom 0.152: v31.75,18.41 v7.62,18.41
AB7  (via drill 0.3)
  Top 0.152: IC2.19 30.55,18.49 v31.12,19.05 32.42,20.36 IC3.18 | IC1.18 16,21.47 v18.41,19.05
  Bottom 0.152: v31.12,19.05 v18.41,19.05
AB8  (via drill 0.3)
  Top 0.152: IC2.18 30.05,19.26 v30.48,19.68 31.66,20.86 IC3.17 | IC1.19 16.8,21.94 v19.05,19.68
  Bottom 0.152: v30.48,19.68 v19.05,19.68
AB9  (via drill 0.3)
  Top 0.152: IC2.8 25.05,22.52 v26.04,23.5 26.9,24.36 IC3.10 | v20.32,23.5 19.28,23.5 IC1.22
  Bottom 0.152: v20.32,23.5 v26.04,23.5
AB10  (via drill 0.3)
  Top 0.152: IC2.7 24.55,23.29 v25.4,24.13 26.13,24.86 IC3.9 | IC1.44 2.4,32.53 4.45,30.48 11.43,30.48 v14.61,27.3
  Bottom 0.152: v14.61,27.3 17.78,24.13 v25.4,24.13
AB11  (via drill 0.3)
  Top 0.152: IC2.6 24.05,24.05 v24.77,24.77 25.36,25.36 IC3.8 | IC1.43 3.2,33 5.08,31.11 12.06,31.11 v15.88,27.3
  Bottom 0.152: v15.88,27.3 18.41,24.77 v24.77,24.77
AB12  (via drill 0.3)
  Top 0.152: IC2.5 23.55,24.82 v24.13,25.4 24.59,25.86 IC3.7 | IC1.42 3.99,33.47 5.72,31.75 12.7,31.75 v17.14,27.3
  Bottom 0.152: v17.14,27.3 19.05,25.4 v24.13,25.4
AB13  (via drill 0.3)
  Top 0.152: IC2.4 23.05,25.59 v23.5,26.04 23.82,26.36 IC3.6 | IC1.39 6.4,34.24 6.98,33.66 12.06,33.66 v18.41,27.3
  Bottom 0.152: v18.41,27.3 19.69,26.04 v23.5,26.04
AB14  (via drill 0.3)
  Top 0.152: IC3.4 23.55,27.36 v22.86,26.67 22.55,26.36 IC2.3 | IC1.28 15.2,31.8 v19.69,27.3
  Bottom 0.152: v19.69,27.3 20.32,26.67 v22.86,26.67
AB15  (via drill 0.3)
  Top 0.152: IC2.2 22.05,27.14 v22.23,27.3 22.78,27.86 IC3.3 | IC1.27 16,32.27 v20.96,27.3
  Bottom 0.152: v22.23,27.3 v20.96,27.3
AB16
  Top 0.152: IC2.1 21.55,27.91 22.01,28.36 | IC1.26 16.8,33.37 21.8,28.36 22.01,28.36 | 22.01,28.36 IC3.2
AB17
  Top 0.152: IC3.1 25.75,28.86 21.55,33.05 | 21.55,33.05 IC2.48 | IC1.25 17.6,33.84 18.41,33.02 21.52,33.02 21.55,33.05
AB18  (via drill 0.3)
  Top 0.152: IC2.17 29.55,20.03 v29.84,20.32 30.89,21.36 IC3.16 | IC1.20 17.6,22.41 v19.69,20.32
  Bottom 0.152: v29.84,20.32 v19.69,20.32
AB19  (via drill 0.3)
  Top 0.152: IC2.16 29.05,20.8 v29.21,20.95 30.12,21.86 IC3.15 | IC1.21 18.39,22.88 v20.32,20.95
  Bottom 0.152: v29.21,20.95 v20.32,20.95
AB20
  Top 0.152: IC2.9 25.55,21.75 27.67,23.86 IC3.11
AB21
  Top 0.152: IC2.10 26.05,21.61 27.8,23.36 IC3.12
AB22
  Top 0.152: IC2.13 27.55,20.57 29.34,22.36 IC3.14
ACC/!WP  (via drill 0.3)
  Top 0.152: IC2.14 28.05,17.58 v28.26,17.78 | R5.1 12.06,19.7 WP.2
  Bottom 0.152: v28.26,17.78 13.97,17.78 WP.2
CLK  (via drill 0.3)
  Top 0.152: IC3.22 34.34,18.36 v34.29,18.41
  Bottom 0.152: v34.29,18.41 33.66,17.78 33.66,16.51 29.21,12.06 22.23,12.06 19.34,9.18 19.34,4.71 X1.V
CR/!W
  Top 0.152: IC3.34 41.81,13.88 40.64,12.7 33.02,12.7 31.12,10.79 20.96,10.79 19.34,9.18 19.34,4.71 X1.18
D0
  Top 0.152: IC3.74 65.62,28.36 82.7,11.28 82.7,4.72 X1.2
D1
  Top 0.152: IC3.72 64.08,27.36 78.74,12.7 78.74,4.72 X1.3
D2
  Top 0.152: IC3.70 62.54,26.36 74.78,14.12 74.78,4.72 X1.4
D3
  Top 0.152: IC3.67 61.5,24.86 70.82,15.54 70.82,4.72 X1.5
D4
  Top 0.152: IC3.65 59.96,23.86 66.86,16.96 66.86,4.71 X1.6
D5
  Top 0.152: IC3.63 58.42,22.86 64.14,17.14 64.14,10.16 62.9,8.93 62.9,4.71 X1.7
D6
  Top 0.152: IC3.60 57.38,21.36 61.59,17.14 61.59,12.06 58.94,9.41 X1.8
D7
  Top 0.152: IC3.58 55.84,20.36 59.05,17.14 59.05,13.34 54.98,9.26 54.98,4.71 X1.9
DB0  (via drill 0.3)
  Top 0.152: v28.57,30.48 31.05,32.96 IC2.29 31.05,36.77 32.39,38.1 35.56,38.1 41.31,32.34 IC3.93 | v12.8,25.5 IC1.14
  Bottom 0.152: v28.57,30.48 15.88,30.48 12.8,27.4 v12.8,25.5
DB1  (via drill 0.3)
  Top 0.152: v27.94,31.11 30.05,33.23 IC2.31 30.05,36.41 32.39,38.73 35.56,38.73 41.81,32.48 IC3.92 | v11.99,25.96 IC1.13
  Bottom 0.152: v27.94,31.11 15.88,31.11 11.99,27.23 v11.99,25.96
DB2  (via drill 0.3)
  Top 0.152: v27.3,31.75 29.05,33.5 IC2.33 29.05,36.04 32.39,39.37 35.56,39.37 42.31,32.62 IC3.91 | v9.59,24.84 IC1.10
  Bottom 0.152: v9.59,24.84 9.52,24.84 9.52,25.4 15.88,31.75 v27.3,31.75
DB3  (via drill 0.3)
  Top 0.152: v26.67,32.38 28.05,33.77 IC2.35 28.05,36.31 31.75,40.01 35.56,40.01 42.81,32.75 IC3.90 | v8.8,25.3 IC1.9
  Bottom 0.152: v26.67,32.38 15.88,32.38 v8.8,25.3
DB4  (via drill 0.3)
  Top 0.152: IC2.38 26.55,37.35 29.84,40.64 v32.39,40.64 35.56,40.64 43.31,32.88 IC3.89 | IC1.31 12.8,35.66 v13.34,36.2
  Bottom 0.152: v13.34,36.2 17.78,40.64 v32.39,40.64
DB5  (via drill 0.3)
  Top 0.152: IC2.40 25.55,36.98 29.84,41.27 v31.75,41.27 35.56,41.27 44.31,32.52 IC3.87 | IC1.32 12.06,34.91 v12.06,36.2
  Bottom 0.152: v12.06,36.2 17.14,41.27 v31.75,41.27
DB6  (via drill 0.3)
  Top 0.152: IC2.42 24.55,36.62 29.84,41.91 v31.12,41.91 35.56,41.91 44.81,32.66 IC3.86 | IC1.35 9.59,36.9 v9.52,36.83
  Bottom 0.152: v9.52,36.83 14.61,41.91 v31.12,41.91
DB7  (via drill 0.3)
  Top 0.152: IC2.44 23.55,36.26 29.84,42.55 v30.48,42.55 35.56,42.55 45.31,32.79 IC3.85 | IC1.36 8.8,36.1 v8.89,36.2
  Bottom 0.152: v8.89,36.2 8.89,37.47 13.97,42.55 v30.48,42.55
GND  (via drill 0.3, 1.5)
  Top 2.286: v86.69,10.79 X1.A | v3.5,10.79 3.48,10.77 X1.Z
  Bottom 2.286: X1.A v86.69,10.79 | v3.5,10.79 3.48,10.77 X1.Z
  other vias: 10.16,36.2 11.43,24.77 47.62,24.13 51.44,15.24 36.2,15.24 36.2,30.48 51.44,30.48 37.47,20.95 41.27,20.95 41.27,29.21
  pour Top: 0,75.56 90.17,75.56 90.17,9.53 0,9.53
  pour Bottom: 0,75.56 90.17,75.56 90.17,9.53 0,9.53
N$1
  Top 0.152: S1.1 27.28,73.64 35.56,65.35 35.56,43.81 | 43.18,36.2 R4.2 | IC3.81 47.31,32.06 43.18,36.2 | 35.56,43.81 43.18,36.2 | 35.56,43.81 8,43.81 S1A.1
N$2
  Top 0.152: IC3.80 47.81,31.94 50.18,34.3 R3.2 50.16,36.21 50.16,43.79 | S2.1 48.92,73.64 50.16,72.39 50.16,43.79 | 50.16,43.79 S2A.1
N$3
  Top 0.152: R1.1 55.88,36.2 LED1A.A 85.72,66.04 LED1.A
N$4
  Top 0.152: IC3.79 48.31,31.8 52.7,36.2 R1.2
N$5  (via drill 0.3)
  Top 0.152: IC3.45 47.31,16.2 TDI.TP
  other vias: 47.62,16.51
N$6  (via drill 0.3)
  Top 0.152: IC3.47 48.31,18.36 TMS.TP
  other vias: 47.62,19.05
N$7  (via drill 0.3)
  Top 0.152: IC3.48 48.81,20.4 TCK.TP
  other vias: 47.62,21.59
N$8  (via drill 0.3)
  Top 0.152: IC3.83 46.31,29.89 46.99,29.21 TDO.TP
  other vias: 47.68,29.21
VR/!W
  Top 0.152: IC3.36 42.81,13.61 41.27,12.06 33.02,12.06 31.12,10.16 24.13,10.16 23.3,9.33 23.3,4.71 X1.17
